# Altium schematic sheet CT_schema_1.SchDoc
size 418 x 356 mm
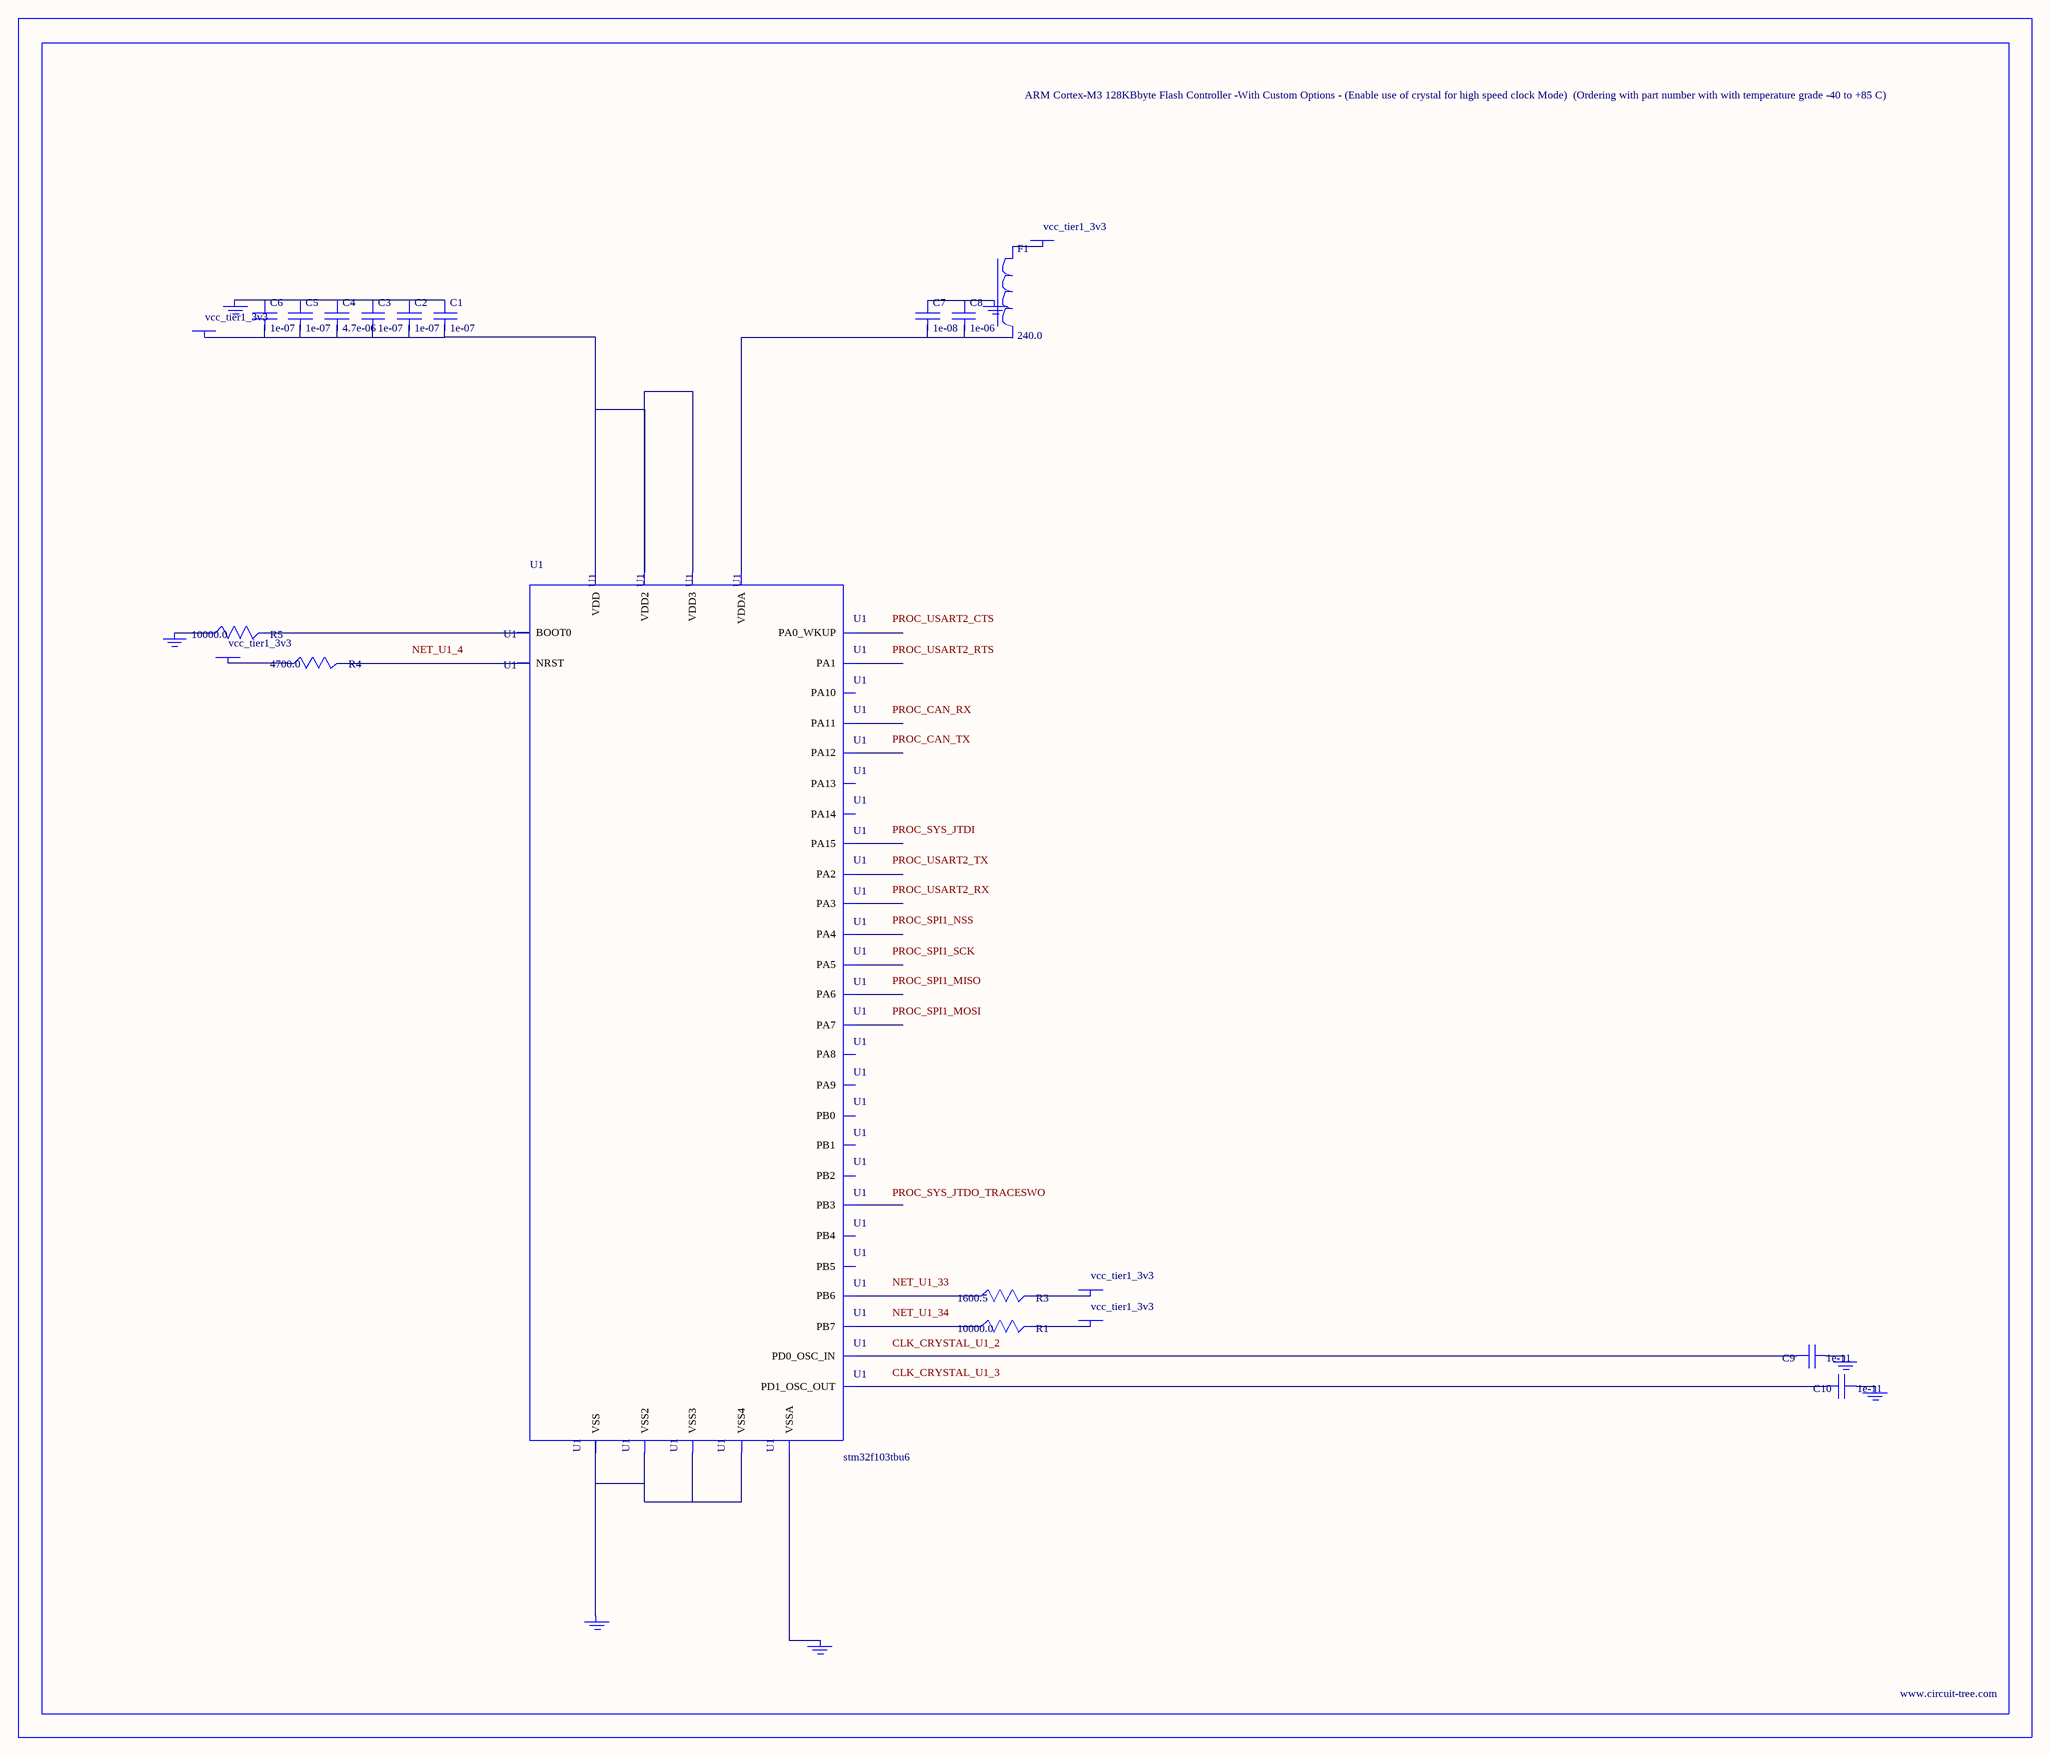
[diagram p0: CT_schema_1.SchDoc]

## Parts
BORDER0  (no value)
C1  1e-07  [C0603]
C2  1e-07  [C0603]
C3  1e-07  [C0603]
C4  4.7e-06  [C0603]
C5  1e-07  [C0603]
C6  1e-07  [C0603]
C7  1e-08  [C0603]
C8  1e-06  [C0603]
C9  1e-11  [C0402]
C10  1e-11  [C0402]
F1  240.0  [L0603]
GND_INSTANCE_0_0  (no value)
GND_INSTANCE_0_1  (no value)
GND_INSTANCE_0_2  (no value)
GND_INSTANCE_0_3  (no value)
GND_INSTANCE_0_4  (no value)
GND_INSTANCE_0_5  (no value)
GND_INSTANCE_0_6  (no value)
POWER_INSTANCE_0_0  vcc_tier1_3v3
POWER_INSTANCE_0_1  vcc_tier1_3v3
POWER_INSTANCE_0_2  vcc_tier1_3v3
POWER_INSTANCE_0_3  vcc_tier1_3v3
POWER_INSTANCE_0_4  vcc_tier1_3v3
R1  10000.0  [R0603]
R3  1600.5  [R0603]
R4  4700.0  [R0603]
R5  10000.0  [R0603]
U1  stm32f103tbu6  [VFQFPN36]

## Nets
NetC1_1: C1.1 C2.1 C3.1 C4.1 C5.1 C6.1 GND_INSTANCE_0_0.0(GND)
NetC1_2: C1.2 C2.2 C3.2 C4.2 C5.2 C6.2 POWER_INSTANCE_0_0.0(PWR) U1.1(VDD) U1.19(VDD2) U1.27(VDD3)
NetC7_1: C7.1 C8.1 GND_INSTANCE_0_4.0(GND)
NetC7_2: C7.2 C8.2 U1.6(VDDA)
NetC9_1: C9.1 GND_INSTANCE_0_1.0(GND)
NetC9_2: C9.2 U1.2(PD0_OSC_IN)
NetC10_1: C10.1 GND_INSTANCE_0_2.0(GND)
NetC10_2: C10.2 U1.3(PD1_OSC_OUT)
NetF1_1: F1.1 POWER_INSTANCE_0_1.0(PWR)
NetGND_INSTANCE_0_3_0: GND_INSTANCE_0_3.0(GND) U1.5(VSSA)
NetGND_INSTANCE_0_5_0: GND_INSTANCE_0_5.0(GND) R5.1
NetGND_INSTANCE_0_6_0: GND_INSTANCE_0_6.0(GND) U1.18(VSS) U1.26(VSS2) U1.36(VSS3) U1.37(VSS4)
NetPOWER_INSTANCE_0_2_0: POWER_INSTANCE_0_2.0(PWR) R4.1
NetPOWER_INSTANCE_0_3_0: POWER_INSTANCE_0_3.0(PWR) R3.2
NetPOWER_INSTANCE_0_4_0: POWER_INSTANCE_0_4.0(PWR) R1.2
NetR1_1: R1.1 U1.34(PB7)
NetR3_1: R3.1 U1.33(PB6)
NetR4_2: R4.2 U1.4(NRST)
NetR5_2: R5.2 U1.35(BOOT0)

Not connected (* = marked no-connect by the designer): F1 2; U1 7(PA0_WKUP) 8(PA1) 9(PA2) 10(PA3) 11(PA4) 12(PA5) 13(PA6) 14(PA7) 15(PB0) 16(PB1) 17(PB2) 20(PA8) 21(PA9) 22(PA10) 23(PA11) 24(PA12) 25(PA13) 28(PA14) 29(PA15) 30(PB3) 31(PB4) 32(PB5)

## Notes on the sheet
- Labels drawn without touching a wire or pin: CLK_CRYSTAL_U1_2, CLK_CRYSTAL_U1_3, NET_U1_4, NET_U1_33, NET_U1_34, PROC_CAN_RX, PROC_CAN_TX, PROC_SPI1_MISO, PROC_SPI1_MOSI, PROC_SPI1_NSS, PROC_SPI1_SCK, PROC_SYS_JTDI, PROC_SYS_JTDO_TRACESWO, PROC_USART2_CTS, PROC_USART2_RTS, PROC_USART2_RX, PROC_USART2_TX

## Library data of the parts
BORDER0 = BORDER_PAGE0
C1-C3 C5 C6 = 06035C104K4Z2A
C4 = GRM188R6YA475KE15D
C7 = 06035C103K4Z2A
C8 = C0603C105K3RACTU
C9 C10 = C0402C100K3GACTU
F1 = Z0603C241ASMST
GND_INSTANCE_0_0-GND_INSTANCE_0_6 = GND
POWER_INSTANCE_0_0-POWER_INSTANCE_0_4 = PWR
R1 R5 = RC0603JR-0710KL
R3 = R3
R4 = RC0603JR-074K7L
